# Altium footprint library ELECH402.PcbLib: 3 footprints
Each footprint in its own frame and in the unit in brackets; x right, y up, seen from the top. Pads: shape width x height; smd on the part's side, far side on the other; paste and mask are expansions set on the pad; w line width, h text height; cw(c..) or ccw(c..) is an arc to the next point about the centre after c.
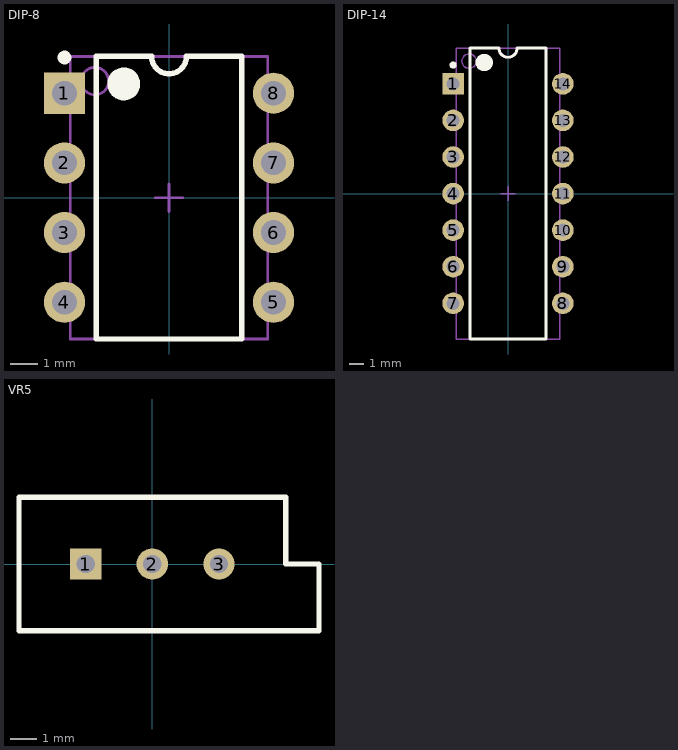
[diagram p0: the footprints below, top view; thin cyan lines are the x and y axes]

## DIP-8 [mm] "DIP, 8-Pin, Row Spacing 7.62 mm, Pitch 2.54 mm"
height 5.33
pads (8):
  rect 1.5x1.5 hole 0.9: 1(-3.81,3.81)
  round 1.5 hole 0.9: 2(-3.81,1.27) 3(-3.81,-1.27) 4(-3.81,-3.81) 5(3.81,-3.81) 6(3.81,-1.27) 7(3.81,1.27) 8(3.81,3.81)
Top Overlay:
  circle w0.6: c-1.65,4.15 r0.3
  circle w0.25: c-3.81,5.11 r0.125
  lines w0.2: -2.65,-5.15 2.65,-5.15 2.65,5.15 0.635,5.15 cw(c0,5.15) -0.635,5.15 -2.65,5.15 -2.65,-5.15
Mechanical 13:
  circle w0.1: c-2.7,4.25 r0.5
  lines w0.1: -3.6,-5.15 3.6,-5.15 3.6,5.15 -3.6,5.15 -3.6,-5.15
Mechanical 15:
  lines w0.1: -0.5,0 0.5,0 ; 0,-0.5 0,0.5
3D body: height 5.33, standoff 0, extent -3.6,-5.15 3.6,5.15

## DIP-14 [mm] "DIP, 14-Pin, Row Spacing 7.62 mm, Pitch 2.54 mm"
height 5.08
pads (14):
  rect 1.5x1.5 hole 0.9: 1(-3.81,7.62)
  round 1.5 hole 0.9: 2(-3.81,5.08) 3(-3.81,2.54) 4(-3.81,0) 5(-3.81,-2.54) 6(-3.81,-5.08) 7(-3.81,-7.62) 8(3.81,-7.62) 9(3.81,-5.08) 10(3.81,-2.54) 11(3.81,0) 12(3.81,2.54) 13(3.81,5.08) 14(3.81,7.62)
Top Overlay:
  circle w0.6: c-1.65,9.1 r0.3
  circle w0.25: c-3.81,8.92 r0.125
  lines w0.2: -2.65,-10.1 2.65,-10.1 2.65,10.1 0.635,10.1 cw(c0,10.1) -0.635,10.1 -2.65,10.1 -2.65,-10.1
Mechanical 13:
  circle w0.1: c-2.7,9.2 r0.5
  lines w0.1: -3.6,-10.1 3.6,-10.1 3.6,10.1 -3.6,10.1 -3.6,-10.1
Mechanical 15:
  lines w0.1: -0.5,0 0.5,0 ; 0,-0.5 0,0.5
3D body: height 5.08, standoff 0, extent -3.6,-10.1 3.6,10.1

## VR5 [mm] "Thru-Hole; 3 Leads"
pads (3):
  rect 1.2x1.2 hole 0.7: 1(-2.54,0)
  round 1.2 hole 0.7: 2(0,0) 3(2.54,0)
Top Overlay:
  lines w0.2: -5.08,-2.54 6.35,-2.54 6.35,0 5.08,0 5.08,2.54 -5.08,2.54 -5.08,-2.54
